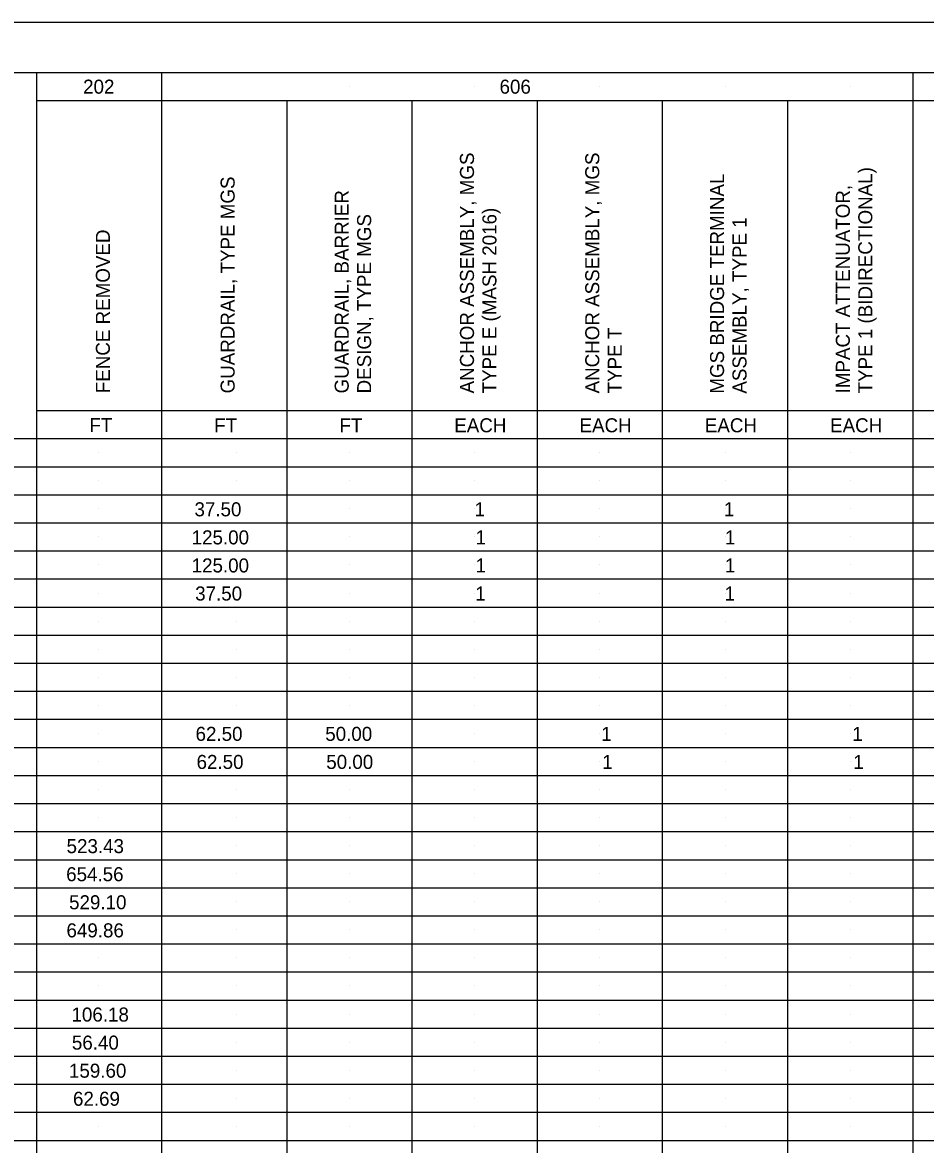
# Model space of a CAD drawing. Extents: x 2073163.9 to 2073197.9, y 634076.5 to 634098.5.
# Drawn here: x 2073172.06 to 2073181.07, y 634087.36 to 634098.55 of the extents above; entities that cross this region are included whole.
import ezdxf

# ---------------------------------------------------------------- set-up
doc = ezdxf.new("R2010")
doc.units = 0
for name, color, linetype in [('SH_Border', 7, 'Continuous'), ('SH_Cut_Line', 7, 'Continuous'), ('SH_Data', 7, 'Continuous'), ('SH_Text', 7, 'Continuous')]:
    doc.layers.add(name, color=color, linetype=linetype)

msp = doc.modelspace()

# ---------------------------------------------------------------- linework, layer by layer
at = {"layer": 'SH_Border'}
msp.add_lwpolyline([(2073165.446, 634098.05), (2073197.446, 634098.05), (2073197.446, 634077.05), (2073165.446, 634077.05)], close=True, dxfattribs=at)
at = {"layer": 'SH_Cut_Line'}
msp.add_lwpolyline([(2073163.946, 634076.55), (2073197.946, 634076.55), (2073197.946, 634098.55), (2073163.946, 634098.55)], close=True, dxfattribs=at)
at = {"layer": 'SH_Data'}
for p, q in [((2073172.201, 634077.05), (2073172.201, 634098.05)), ((2073173.451, 634077.054), (2073173.451, 634098.05)), ((2073180.946, 634077.598), (2073180.946, 634098.05)), ((2073175.321, 634097.91), (2073175.321, 634097.91)), ((2073176.571, 634097.91), (2073176.571, 634097.91)), ((2073177.821, 634097.91), (2073177.821, 634097.91)), ((2073179.071, 634097.91), (2073179.071, 634097.91)), ((2073180.321, 634097.91), (2073180.321, 634097.91)), ((2073172.201, 634077.054), (2073172.201, 634097.774)), ((2073172.201, 634097.77), (2073195.946, 634097.77)), ((2073174.701, 634077.052), (2073174.701, 634097.772)), ((2073175.946, 634077.05), (2073175.946, 634097.77)), ((2073177.196, 634077.05), (2073177.196, 634097.77)), ((2073178.446, 634077.05), (2073178.446, 634097.77)), ((2073179.696, 634077.05), (2073179.696, 634097.77)), ((2073180.946, 634077.05), (2073180.946, 634097.77)), ((2073172.201, 634094.678), (2073195.946, 634094.678)), ((2073175.321, 634094.538), (2073175.321, 634094.538)), ((2073176.571, 634094.538), (2073176.571, 634094.538)), ((2073177.821, 634094.538), (2073177.821, 634094.538)), ((2073179.071, 634094.538), (2073179.071, 634094.538)), ((2073180.321, 634094.538), (2073180.321, 634094.538)), ((2073165.446, 634094.398), (2073195.946, 634094.398)), ((2073172.821, 634094.258), (2073172.821, 634094.258)), ((2073174.196, 634094.258), (2073174.196, 634094.258)), ((2073175.321, 634094.258), (2073175.321, 634094.258)), ((2073176.571, 634094.258), (2073176.571, 634094.258)), ((2073177.821, 634094.258), (2073177.821, 634094.258)), ((2073179.071, 634094.258), (2073179.071, 634094.258)), ((2073180.321, 634094.258), (2073180.321, 634094.258)), ((2073165.44, 634094.118), (2073195.948, 634094.118)), ((2073172.821, 634093.978), (2073172.821, 634093.978)), ((2073174.196, 634093.978), (2073174.196, 634093.978)), ((2073175.321, 634093.978), (2073175.321, 634093.978)), ((2073176.571, 634093.978), (2073176.571, 634093.978)), ((2073177.821, 634093.978), (2073177.821, 634093.978)), ((2073179.071, 634093.978), (2073179.071, 634093.978)), ((2073180.321, 634093.978), (2073180.321, 634093.978)), ((2073165.45, 634093.838), (2073195.947, 634093.838)), ((2073172.821, 634093.698), (2073172.821, 634093.698)), ((2073174.196, 634093.698), (2073174.196, 634093.698)), ((2073175.321, 634093.698), (2073175.321, 634093.698)), ((2073176.571, 634093.698), (2073176.571, 634093.698)), ((2073177.821, 634093.698), (2073177.821, 634093.698)), ((2073179.071, 634093.698), (2073179.071, 634093.698)), ((2073180.321, 634093.698), (2073180.321, 634093.698)), ((2073165.45, 634093.558), (2073195.947, 634093.558)), ((2073172.821, 634093.418), (2073172.821, 634093.418)), ((2073174.196, 634093.418), (2073174.196, 634093.418)), ((2073175.321, 634093.418), (2073175.321, 634093.418)), ((2073176.571, 634093.418), (2073176.571, 634093.418)), ((2073177.821, 634093.418), (2073177.821, 634093.418)), ((2073179.071, 634093.418), (2073179.071, 634093.418)), ((2073180.321, 634093.418), (2073180.321, 634093.418)), ((2073165.447, 634093.278), (2073195.949, 634093.278)), ((2073172.821, 634093.138), (2073172.821, 634093.138)), ((2073174.196, 634093.138), (2073174.196, 634093.138)), ((2073175.321, 634093.138), (2073175.321, 634093.138)), ((2073176.571, 634093.138), (2073176.571, 634093.138)), ((2073177.821, 634093.138), (2073177.821, 634093.138)), ((2073179.071, 634093.138), (2073179.071, 634093.138)), ((2073180.321, 634093.138), (2073180.321, 634093.138)), ((2073165.444, 634092.998), (2073195.947, 634092.998)), ((2073172.821, 634092.858), (2073172.821, 634092.858)), ((2073174.196, 634092.858), (2073174.196, 634092.858)), ((2073175.321, 634092.858), (2073175.321, 634092.858)), ((2073176.571, 634092.858), (2073176.571, 634092.858)), ((2073177.821, 634092.858), (2073177.821, 634092.858)), ((2073179.071, 634092.858), (2073179.071, 634092.858)), ((2073180.321, 634092.858), (2073180.321, 634092.858)), ((2073165.454, 634092.718), (2073195.947, 634092.718)), ((2073172.821, 634092.578), (2073172.821, 634092.578)), ((2073174.196, 634092.578), (2073174.196, 634092.578)), ((2073175.321, 634092.578), (2073175.321, 634092.578)), ((2073176.571, 634092.578), (2073176.571, 634092.578)), ((2073177.821, 634092.578), (2073177.821, 634092.578)), ((2073179.071, 634092.578), (2073179.071, 634092.578)), ((2073180.321, 634092.578), (2073180.321, 634092.578)), ((2073165.45, 634092.438), (2073195.943, 634092.438)), ((2073172.821, 634092.298), (2073172.821, 634092.298)), ((2073174.196, 634092.298), (2073174.196, 634092.298)), ((2073175.321, 634092.298), (2073175.321, 634092.298)), ((2073176.571, 634092.298), (2073176.571, 634092.298)), ((2073177.821, 634092.298), (2073177.821, 634092.298)), ((2073179.071, 634092.298), (2073179.071, 634092.298)), ((2073180.321, 634092.298), (2073180.321, 634092.298)), ((2073165.448, 634092.158), (2073195.943, 634092.158)), ((2073172.821, 634092.018), (2073172.821, 634092.018)), ((2073174.196, 634092.018), (2073174.196, 634092.018)), ((2073175.321, 634092.018), (2073175.321, 634092.018)), ((2073176.571, 634092.018), (2073176.571, 634092.018)), ((2073177.821, 634092.018), (2073177.821, 634092.018)), ((2073179.071, 634092.018), (2073179.071, 634092.018)), ((2073180.321, 634092.018), (2073180.321, 634092.018)), ((2073165.448, 634091.878), (2073195.943, 634091.878)), ((2073172.821, 634091.738), (2073172.821, 634091.738)), ((2073174.196, 634091.738), (2073174.196, 634091.738)), ((2073175.321, 634091.738), (2073175.321, 634091.738)), ((2073176.571, 634091.738), (2073176.571, 634091.738)), ((2073177.821, 634091.738), (2073177.821, 634091.738)), ((2073179.071, 634091.738), (2073179.071, 634091.738)), ((2073180.321, 634091.738), (2073180.321, 634091.738)), ((2073165.448, 634091.598), (2073195.948, 634091.598)), ((2073172.821, 634091.458), (2073172.821, 634091.458)), ((2073174.196, 634091.458), (2073174.196, 634091.458)), ((2073175.321, 634091.458), (2073175.321, 634091.458)), ((2073176.571, 634091.458), (2073176.571, 634091.458)), ((2073177.821, 634091.458), (2073177.821, 634091.458)), ((2073179.071, 634091.458), (2073179.071, 634091.458)), ((2073180.321, 634091.458), (2073180.321, 634091.458)), ((2073165.451, 634091.318), (2073195.939, 634091.318)), ((2073165.451, 634091.318), (2073195.944, 634091.318)), ((2073172.821, 634091.178), (2073172.821, 634091.178)), ((2073174.196, 634091.178), (2073174.196, 634091.178)), ((2073175.321, 634091.178), (2073175.321, 634091.178)), ((2073176.571, 634091.178), (2073176.571, 634091.178)), ((2073177.821, 634091.178), (2073177.821, 634091.178)), ((2073179.071, 634091.178), (2073179.071, 634091.178)), ((2073180.321, 634091.178), (2073180.321, 634091.178)), ((2073165.448, 634091.038), (2073195.944, 634091.038)), ((2073172.821, 634090.898), (2073172.821, 634090.898)), ((2073174.196, 634090.898), (2073174.196, 634090.898)), ((2073175.321, 634090.898), (2073175.321, 634090.898)), ((2073176.571, 634090.898), (2073176.571, 634090.898)), ((2073177.821, 634090.898), (2073177.821, 634090.898)), ((2073179.071, 634090.898), (2073179.071, 634090.898)), ((2073180.321, 634090.898), (2073180.321, 634090.898)), ((2073165.445, 634090.758), (2073195.942, 634090.758)), ((2073172.821, 634090.618), (2073172.821, 634090.618)), ((2073174.196, 634090.618), (2073174.196, 634090.618)), ((2073175.321, 634090.618), (2073175.321, 634090.618)), ((2073176.571, 634090.618), (2073176.571, 634090.618)), ((2073177.821, 634090.618), (2073177.821, 634090.618)), ((2073179.071, 634090.618), (2073179.071, 634090.618)), ((2073180.321, 634090.618), (2073180.321, 634090.618)), ((2073165.442, 634090.478), (2073195.946, 634090.478)), ((2073172.821, 634090.338), (2073172.821, 634090.338)), ((2073174.196, 634090.338), (2073174.196, 634090.338)), ((2073175.321, 634090.338), (2073175.321, 634090.338)), ((2073176.571, 634090.338), (2073176.571, 634090.338)), ((2073177.821, 634090.338), (2073177.821, 634090.338)), ((2073179.071, 634090.338), (2073179.071, 634090.338)), ((2073180.321, 634090.338), (2073180.321, 634090.338)), ((2073165.442, 634090.198), (2073195.946, 634090.198)), ((2073172.821, 634090.058), (2073172.821, 634090.058)), ((2073174.196, 634090.058), (2073174.196, 634090.058)), ((2073175.321, 634090.058), (2073175.321, 634090.058)), ((2073176.571, 634090.058), (2073176.571, 634090.058)), ((2073177.821, 634090.058), (2073177.821, 634090.058)), ((2073179.071, 634090.058), (2073179.071, 634090.058)), ((2073180.321, 634090.058), (2073180.321, 634090.058)), ((2073165.446, 634089.918), (2073195.946, 634089.918)), ((2073172.821, 634089.778), (2073172.821, 634089.778)), ((2073174.196, 634089.778), (2073174.196, 634089.778)), ((2073175.321, 634089.778), (2073175.321, 634089.778)), ((2073176.571, 634089.778), (2073176.571, 634089.778)), ((2073177.821, 634089.778), (2073177.821, 634089.778)), ((2073179.071, 634089.778), (2073179.071, 634089.778)), ((2073180.321, 634089.778), (2073180.321, 634089.778)), ((2073165.446, 634089.638), (2073195.946, 634089.638)), ((2073172.821, 634089.498), (2073172.821, 634089.498)), ((2073174.196, 634089.498), (2073174.196, 634089.498)), ((2073175.321, 634089.498), (2073175.321, 634089.498)), ((2073176.571, 634089.498), (2073176.571, 634089.498)), ((2073177.821, 634089.498), (2073177.821, 634089.498)), ((2073179.071, 634089.498), (2073179.071, 634089.498)), ((2073180.321, 634089.498), (2073180.321, 634089.498)), ((2073165.446, 634089.358), (2073195.946, 634089.358)), ((2073172.821, 634089.218), (2073172.821, 634089.218)), ((2073174.196, 634089.218), (2073174.196, 634089.218)), ((2073175.321, 634089.218), (2073175.321, 634089.218)), ((2073176.571, 634089.218), (2073176.571, 634089.218)), ((2073177.821, 634089.218), (2073177.821, 634089.218)), ((2073179.071, 634089.218), (2073179.071, 634089.218)), ((2073180.321, 634089.218), (2073180.321, 634089.218)), ((2073165.446, 634089.078), (2073195.946, 634089.078)), ((2073172.821, 634088.938), (2073172.821, 634088.938)), ((2073174.196, 634088.938), (2073174.196, 634088.938)), ((2073175.321, 634088.938), (2073175.321, 634088.938)), ((2073176.571, 634088.938), (2073176.571, 634088.938)), ((2073177.821, 634088.938), (2073177.821, 634088.938)), ((2073179.071, 634088.938), (2073179.071, 634088.938)), ((2073180.321, 634088.938), (2073180.321, 634088.938)), ((2073165.446, 634088.798), (2073195.946, 634088.798)), ((2073172.821, 634088.658), (2073172.821, 634088.658)), ((2073174.196, 634088.658), (2073174.196, 634088.658)), ((2073175.321, 634088.658), (2073175.321, 634088.658)), ((2073176.571, 634088.658), (2073176.571, 634088.658)), ((2073177.821, 634088.658), (2073177.821, 634088.658)), ((2073179.071, 634088.658), (2073179.071, 634088.658)), ((2073180.321, 634088.658), (2073180.321, 634088.658)), ((2073165.446, 634088.518), (2073195.946, 634088.518)), ((2073172.821, 634088.378), (2073172.821, 634088.378)), ((2073174.196, 634088.378), (2073174.196, 634088.378)), ((2073175.321, 634088.378), (2073175.321, 634088.378)), ((2073176.571, 634088.378), (2073176.571, 634088.378)), ((2073177.821, 634088.378), (2073177.821, 634088.378)), ((2073179.071, 634088.378), (2073179.071, 634088.378)), ((2073180.321, 634088.378), (2073180.321, 634088.378)), ((2073165.446, 634088.238), (2073195.946, 634088.238)), ((2073172.821, 634088.098), (2073172.821, 634088.098)), ((2073174.196, 634088.098), (2073174.196, 634088.098)), ((2073175.321, 634088.098), (2073175.321, 634088.098)), ((2073176.571, 634088.098), (2073176.571, 634088.098)), ((2073177.821, 634088.098), (2073177.821, 634088.098)), ((2073179.071, 634088.098), (2073179.071, 634088.098)), ((2073180.321, 634088.098), (2073180.321, 634088.098)), ((2073165.446, 634087.958), (2073195.946, 634087.958)), ((2073172.821, 634087.818), (2073172.821, 634087.818)), ((2073174.196, 634087.818), (2073174.196, 634087.818)), ((2073175.321, 634087.818), (2073175.321, 634087.818)), ((2073176.571, 634087.818), (2073176.571, 634087.818)), ((2073177.821, 634087.818), (2073177.821, 634087.818)), ((2073179.071, 634087.818), (2073179.071, 634087.818)), ((2073180.321, 634087.818), (2073180.321, 634087.818)), ((2073165.446, 634087.678), (2073195.946, 634087.678)), ((2073172.821, 634087.538), (2073172.821, 634087.538)), ((2073174.196, 634087.538), (2073174.196, 634087.538)), ((2073175.321, 634087.538), (2073175.321, 634087.538)), ((2073176.571, 634087.538), (2073176.571, 634087.538)), ((2073177.821, 634087.538), (2073177.821, 634087.538)), ((2073179.071, 634087.538), (2073179.071, 634087.538)), ((2073180.321, 634087.538), (2073180.321, 634087.538)), ((2073165.446, 634087.398), (2073195.946, 634087.398))]:
    msp.add_line(p, q, dxfattribs=at)

# ---------------------------------------------------------------- texts
at = {"layer": 'SH_Text'}
for s, rotation, p in [('202', 0.0001, (2073172.664, 634097.839)), ('606', 0.0001, (2073176.819, 634097.839)), ('ANCHOR ASSEMBLY, MGS', 90.0001, (2073176.564, 634094.849)), ('ANCHOR ASSEMBLY, MGS', 90.0001, (2073177.814, 634094.849)), ('TYPE 1 (BIDIRECTIONAL)', 90.0001, (2073180.538, 634094.849)), ('GUARDRAIL, TYPE MGS', 90.0001, (2073174.176, 634094.849)), ('MGS BRIDGE TERMINAL', 90.0001, (2073179.059, 634094.847)), ('GUARDRAIL, BARRIER', 90.0001, (2073175.314, 634094.849)), ('IMPACT ATTENUATOR, ', 90.0001, (2073180.314, 634094.849)), ('DESIGN, TYPE MGS', 90.0001, (2073175.538, 634094.849)), ('TYPE E (MASH 2016)', 90.0001, (2073176.788, 634094.849)), ('ASSEMBLY, TYPE 1', 90.0001, (2073179.283, 634094.847)), ('FENCE REMOVED', 90.0001, (2073172.931, 634094.851)), ('TYPE T', 90.0001, (2073178.038, 634094.849)), ('FT', 0.0001, (2073172.727, 634094.463)), ('FT', 0.0001, (2073173.972, 634094.461)), ('FT', 0.0001, (2073175.222, 634094.461)), ('EACH', 0.0001, (2073176.367, 634094.461)), ('EACH', 0.0001, (2073177.617, 634094.461)), ('EACH', 0.0001, (2073178.867, 634094.461)), ('EACH', 0.0001, (2073180.117, 634094.461)), ('37.50', 0.0001, (2073173.775, 634093.623)), ('1', 0.0001, (2073176.57, 634093.623)), ('1', 0.0001, (2073179.057, 634093.623)), ('125.00', 0.0001, (2073173.747, 634093.343)), ('1', 0.0001, (2073176.58, 634093.343)), ('1', 0.0001, (2073179.068, 634093.343)), ('125.00', 0.0001, (2073173.747, 634093.063)), ('1', 0.0001, (2073176.58, 634093.063)), ('1', 0.0001, (2073179.068, 634093.063)), ('37.50', 0.0001, (2073173.782, 634092.783)), ('1', 0.0001, (2073176.577, 634092.783)), ('1', 0.0001, (2073179.064, 634092.783)), ('62.50', 0.0001, (2073173.786, 634091.383)), ('50.00', 0.0001, (2073175.08, 634091.383)), ('1', 0.0001, (2073177.834, 634091.383)), ('1', 0.0001, (2073180.339, 634091.383)), ('62.50', 0.0001, (2073173.796, 634091.103)), ('50.00', 0.0001, (2073175.09, 634091.103)), ('1', 0.0001, (2073177.844, 634091.103)), ('1', 0.0001, (2073180.349, 634091.103)), ('523.43', 0.0001, (2073172.499, 634090.263)), ('654.56', 0.0001, (2073172.495, 634089.983)), ('529.10', 0.0001, (2073172.524, 634089.703)), ('649.86', 0.0001, (2073172.498, 634089.423)), ('106.18', 0.0001, (2073172.548, 634088.583)), ('56.40', 0.0001, (2073172.552, 634088.303)), ('159.60', 0.0001, (2073172.523, 634088.023)), ('62.69', 0.0001, (2073172.563, 634087.743))]:
    msp.add_text(s, height=0.14, rotation=rotation, dxfattribs=at).set_placement(p)

doc.saveas('drawing.dxf')
